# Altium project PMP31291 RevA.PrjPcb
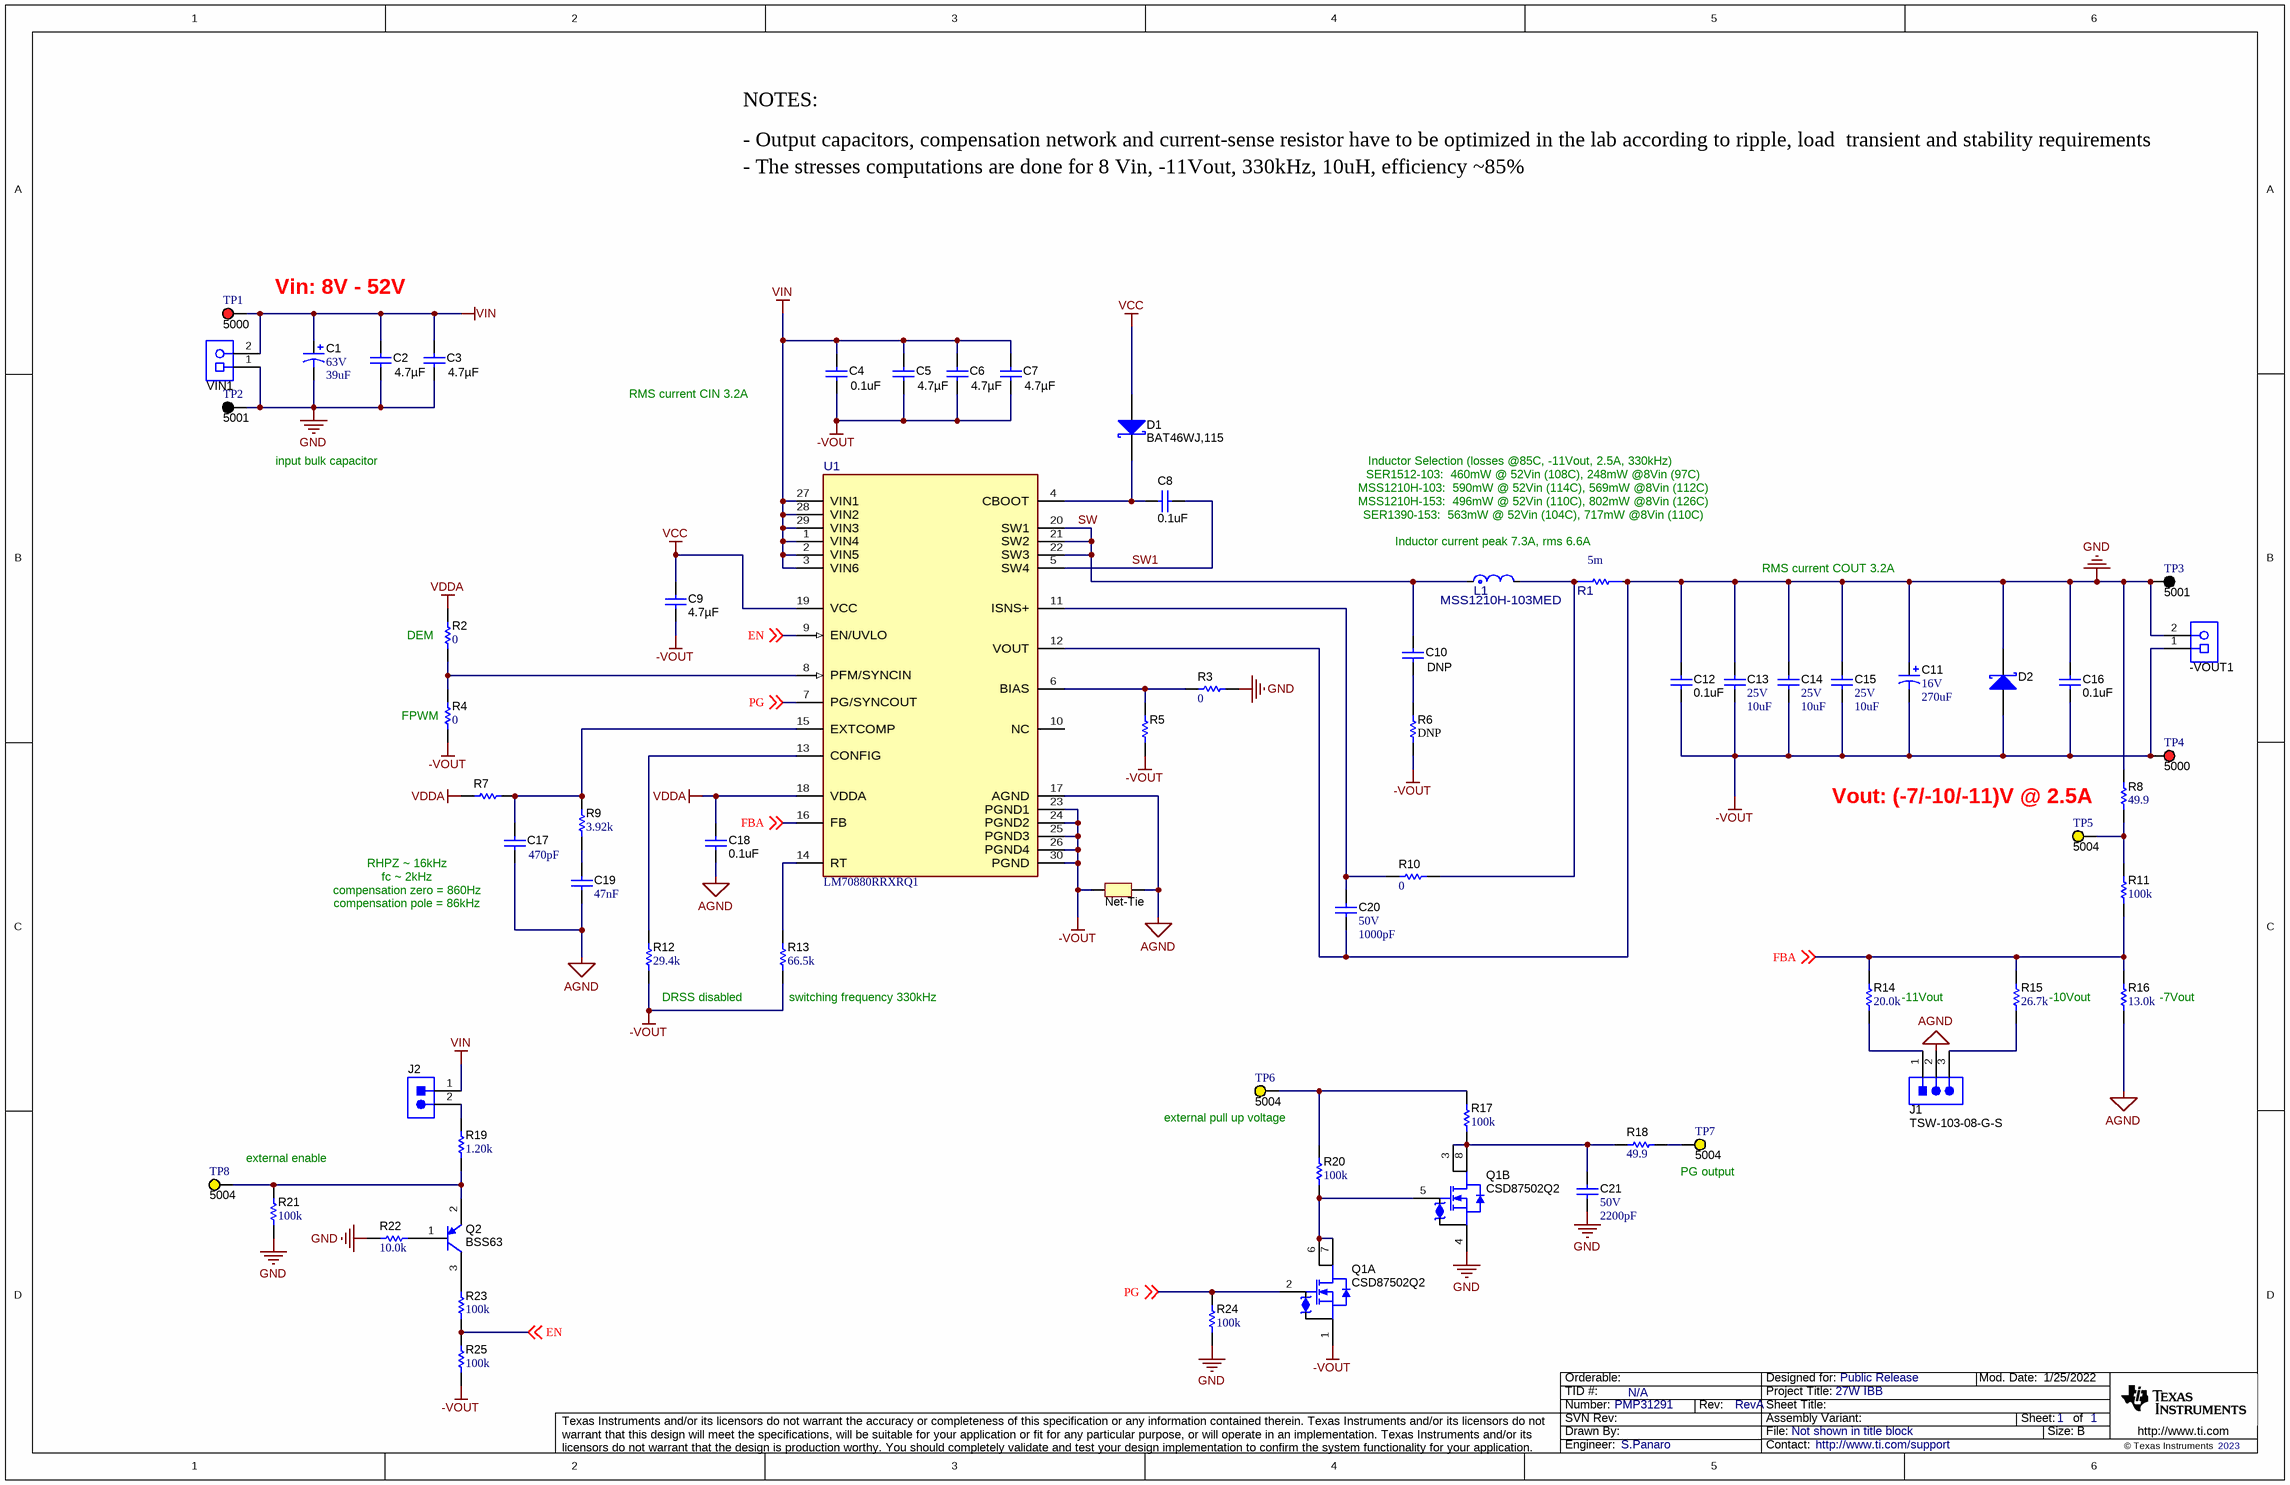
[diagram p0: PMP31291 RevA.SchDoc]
CopyrightYear: 2023; PCB_Layout: S.Panaro; PCB_Rev: RevA; PRJ_Customer: Public Release; PRJ_Engineer: S.Panaro; PRJ_Number: PMP31291; PRJ_Title: 27W IBB; SCH_Rev: RevA; TechSupport: http://www.ti.com/support; TID: N/A
1 sheet, 65 parts. Net scope: global (net labels, ports and power ports of the same name join across sheets).
Board file: PMP31291 RevA.PcbDoc

## Sheet PMP31291 RevA.SchDoc
size 431 x 279 mm; Date: Not shown in title block; ApprovedBy: Not shown in title block; CheckedBy: Not shown in title block; Author: Not shown in title block; CompanyName: Not shown in title block; Engineer: Not shown in title block; Organization: Not shown in title block; Address1: Not shown in title block; Address2: Not shown in title block; Address3: Not shown in title block; Address4: Not shown in title block; DocumentNumber: 1; Revision: Use project parameter SCH_Rev; SheetNumber: 1; SheetTotal: 1; PageSetup: Record=PageOptions¦CenterHorizontal=True¦CenterVertical=True¦PrintScale=1.00¦XCorrection=1.00¦YCorrection=1.00¦PrintKind=0¦BorderSize=5000000¦LeftOffset=0¦BottomOffset=0¦Orientation=2¦PaperLength=1000¦PaperWidth=1000¦Scale=100¦PaperSource=15¦PrintQuality=600¦MediaType=1¦DitherType=10¦PaperKind=Letter¦PrintScaleMode=1

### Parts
-VOUT1  ED120/2DS  [On-Shore_ED120_2DS]  (value not drawn)
C1  VDC_V: 63V  ValueDisplayed: 39uF  [SXV_E12]  (hidden comment: 63SXV39M)
C2  ValueDisplayed: 4.7µF  [1210_220L]  (hidden comment: CL32Y475KCIVPNE)
C3  ValueDisplayed: 4.7µF  [1210_220L]  (hidden comment: CL32Y475KCIVPNE)
C4  value 0.1uF  [0603_HV]  (hidden comment: GCJ188R72A104KA01D)
C5  ValueDisplayed: 4.7µF  [1210_220L]  (hidden comment: CL32Y475KCIVPNE)
C6  ValueDisplayed: 4.7µF  [1210_220L]  (hidden comment: CL32Y475KCIVPNE)
C7  ValueDisplayed: 4.7µF  [1210_220L]  (hidden comment: CL32Y475KCIVPNE)
C8  ValueDisplayed: 0.1uF  [0402L]  (hidden comment: GRM155R71E104KE14D)
C9  Cap_F: 4.7µF  [0603L]  (hidden comment: GRM188Z71A475ME15D)
C10  ValueDisplayed: DNP  [0603_HV]  (hidden comment: GRM1885C2A101JA01D)
C11  VDC_V: 16V  ValueDisplayed: 270uF  [SM_RADIAL_6.3AMM]  (hidden comment: 16SVPG270MX)
C12  ValueDisplayed: 0.1uF  [0402L]  (hidden comment: GRM155R71E104KE14D)
C13  VDC_V: 25V  ValueDisplayed: 10uF  [1206_180]  (hidden comment: CL31B106KAHVPNE)
C14  VDC_V: 25V  ValueDisplayed: 10uF  [1206_180]  (hidden comment: CL31B106KAHVPNE)
C15  VDC_V: 25V  ValueDisplayed: 10uF  [1206_180]  (hidden comment: CL31B106KAHVPNE)
C16  ValueDisplayed: 0.1uF  [0402L]  (hidden comment: GRM155R71E104KE14D)
C17  ValueDisplayed: 470pF  [0402]  (hidden comment: GCM155R71H471KA37D)
C18  ValueDisplayed: 0.1uF  [0402L]  (hidden comment: GRM155R71E104KE14D)
C19  Cap_F: 47nF  [0603]  (hidden comment: GCM188R71E473KA37D)
C20  VDC_V: 50V  ValueDisplayed: 1000pF  [0402]  (hidden comment: CGA2B2C0G1H102J050BA)
C21  VDC_V: 50V  ValueDisplayed: 2200pF  [0402]  (hidden comment: CL05B222JB5NNNC)
D1  BAT46WJ,115  [SOD-323F]
D2  BAT54T1G  [SOD-123]  (value not drawn)
J1  TSW-103-08-G-S  [Samtec_TSW-103-08-x-S]
J2  961102-6804-AR  [3M_961102-68]  (value not drawn)
L1  MSS1210H-103MED  [FP-MSS1210H-103MED_SMT2_12MM0_12MM0-MFG]
NT1  Net-Tie  [Net-Tie_10milWide_30milLong]  (net tie, no BOM)
Q1  CSD87502Q2  [DQK0006B]  (parts A,B of 2)
Q2  BSS63  [SOT-23]
R1  value 5m  [FP-RLM-1632W-4F-R005-FNH_0612-MFG]  (hidden comment: ERJB2DJR005V)
R2  ValueDisplayed: 0  [0402]  (hidden comment: MCR01MZPJ000)
R3  ValueDisplayed: 0  [0402]  (hidden comment: MCR01MZPJ000)
R4  ValueDisplayed: 0  [0402]  (hidden comment: MCR01MZPJ000)
R5  MCR01MZPJ000  [0402]  (value not drawn)
R6  ValueDisplayed: DNP  [0603_HV]  (hidden comment: CRCW06032R00FKEA)
R7  RC1005F104CS  [0402]  (value not drawn)
R8  ValueDisplayed: 49.9  [0402]  (hidden comment: RC0402FR-0749R9L)
R9  ValueDisplayed: 3.92k  [0402]  (hidden comment: CRCW04023K92FKED)
R10  ValueDisplayed: 0  [0402]  (hidden comment: MCR01MZPJ000)
R11  ValueDisplayed: 100k  [0402]  (hidden comment: RC1005F104CS)
R12  ValueDisplayed: 29.4k  [0402]  (hidden comment: CRCW040229K4FKED)
R13  ValueDisplayed: 66.5k  [0402]  (hidden comment: CRCW040266K5FKED)
R14  ValueDisplayed: 20.0k  [0402]  (hidden comment: CRCW040220K0FKED)
R15  ValueDisplayed: 26.7k  [0402]  (hidden comment: CRCW040226K7FKED)
R16  ValueDisplayed: 13.0k  [0402]  (hidden comment: CRCW040213K0FKED)
R17  ValueDisplayed: 100k  [0402]  (hidden comment: RC1005F104CS)
R18  ValueDisplayed: 49.9  [0402]  (hidden comment: RC0402FR-0749R9L)
R19  ValueDisplayed: 1.20k  [0603_HV]  (hidden comment: RC0603FR-071K2L)
R20  ValueDisplayed: 100k  [0402]  (hidden comment: RC1005F104CS)
R21  ValueDisplayed: 100k  [0603_HV]  (hidden comment: RC0603FR-07100KL)
R22  ValueDisplayed: 10.0k  [0603_HV]  (hidden comment: M55342K12B10E0T)
R23  ValueDisplayed: 100k  [0603_HV]  (hidden comment: RC0603FR-07100KL)
R24  ValueDisplayed: 100k  [0402]  (hidden comment: RC1005F104CS)
R25  ValueDisplayed: 100k  [0603_HV]  (hidden comment: RC0603FR-07100KL)
TP1  5000  [Keystone5000]
TP2  5001  [Keystone5001]
TP3  5001  [Keystone5001]
TP4  5000  [Keystone5000]
TP5  5004  [Keystone5004]
TP6  5004  [Keystone5004]
TP7  5004  [Keystone5004]
TP8  5004  [Keystone5004]
U1  LM70880RRXRQ1  [RRX0029B-MFG]
VIN1  ED120/2DS  [On-Shore_ED120_2DS]  (value not drawn)

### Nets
-VOUT: -VOUT1.1 C4.2 C5.2 C6.2 C7.2 C9.2 C11.2(-) C12.1 C13.2 C14.2 C15.2 C16.1 D2.2(A) NT1.1 Q1.1(S1) R4.1 R5.1 R6.2 R12.1 R13.1 R25.1 TP4.1 U1.23(PGND1) U1.24(PGND2) U1.25(PGND3) U1.26(PGND4) U1.30(PGND)
AGND: C17.2 C18.1 C19.2 J1.2 NT1.2 R16.1 U1.17(AGND)
GND: -VOUT1.2 C1.2(-) C2.2 C3.2 C11.1(+) C12.2 C13.1 C14.1 C15.1 C16.2 C20.2 C21.2 D2.1(K) Q1.4(S2) R1.2 R3.2 R8.2 R21.1 R22.1 R24.1 TP2.1 TP3.1 U1.12(VOUT) VIN1.1
VCC: C9.1 D1.2(A) U1.19(VCC)
VDDA: C18.2 R2.2 R7.2 U1.18(VDDA)
VIN: C1.1(+) C2.1 C3.1 C4.1 C5.1 C6.1 C7.1 J2.1 TP1.1 U1.1(VIN4) U1.2(VIN5) U1.3(VIN6) U1.27(VIN1) U1.28(VIN2) U1.29(VIN3) VIN1.2
CONFIG: R12.2 U1.13(CONFIG)
EN: R23.1 R25.2 U1.9(EN/UVLO) ; off-sheet EN
FBA: R11.1 R14.2 R15.2 R16.2 U1.16(FB) ; off-sheet FBA
PG: Q1.2(G1) R24.2 U1.7(PG/SYNCOUT) ; off-sheet PG
RT: R13.2 U1.14(RT)
SW: C10.1 L1.1 U1.20(SW1) U1.21(SW2) U1.22(SW3)
SW1: C8.2 U1.5(SW4)
NetC8_1: C8.1 D1.1(K) U1.4(CBOOT)
NetC10_2: C10.2 R6.1
NetC17_1: C17.1 R7.1 R9.2 U1.15(EXTCOMP)
NetC19_1: C19.1 R9.1
NetC20_1: C20.1 R10.1 U1.11(ISNS+)
NetC21_1: C21.1 Q1.3(D2) Q1.8(D2) R17.1 R18.2
NetJ1_1: J1.1 R14.1
NetJ1_3: J1.3 R15.1
NetJ2_2: J2.2 R19.2
NetL1_2: L1.2 R1.1 R10.2
NetQ1_5: Q1.5(G2) Q1.6(D1) Q1.7(D1) R20.1
NetQ2_1: Q2.1(B) R22.2
NetQ2_2: Q2.2(E) R19.1 R21.2 TP8.1
NetQ2_3: Q2.3(C) R23.2
NetR2_1: R2.1 R4.2 U1.8(PFM/SYNCIN)
NetR3_1: R3.1 R5.2 U1.6(BIAS)
NetR8_1: R8.1 R11.2 TP5.1
NetR17_2: R17.2 R20.2 TP6.1
NetR18_1: R18.1 TP7.1

Not connected (* = marked no-connect by the designer): U1 10(NC)

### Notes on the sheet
- NOTES:
- - Output capacitors, compensation network and current-sense resistor have to be optimized in the lab according to ripple, load  transient and stability requirements
- - The stresses computations are done for 8 Vin, -11Vout, 330kHz, 10uH, efficiency ~85%
- Vin: 8V - 52V
- RMS current CIN 3.2A
- input bulk capacitor
- Inductor Selection (losses @85C, -11Vout, 2.5A, 330kHz)
- SER1512-103:  460mW @ 52Vin (108C), 248mW @8Vin (97C)
- MSS1210H-103:  590mW @ 52Vin (114C), 569mW @8Vin (112C)
- MSS1210H-153:  496mW @ 52Vin (110C), 802mW @8Vin (126C)
- Inductor current peak 7.3A, rms 6.6A
- SER1390-153:  563mW @ 52Vin (104C), 717mW @8Vin (110C)
- RMS current COUT 3.2A
- (near R2) DEM
- (near R4) FPWM
- Vout: (-7/-10/-11)V @ 2.5A
- RHPZ ~ 16kHz
- fc ~ 2kHz
- (near C17) compensation zero = 860Hz
- compensation pole = 86kHz
- (near R12) DRSS disabled
- (near R13) switching frequency 330kHz
- (near R14) -11Vout
- -10Vout
- (near R16) -7Vout
- external enable
- (near TP6) external pull up voltage
- PG output
- Labels drawn without touching a wire or pin: EN/UVLO

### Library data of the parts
-VOUT1 VIN1 = CMP-0074910-1: Terminal Block, 5.08 mm, 2x1, Brass, TH; Manufacturer: On-Shore Technology; Cert_VDE: Y; CNHeader: False; Current_A: 15A; Green_Lifecycle: Not Set; Shrouded: N; Gender: Female; Green_REACh: Incomplete; Voltage_V: 300V; Row_Count: 1; Pitch_mm: 5.08; CT: True
C1 = CMP-0012145-3: CAP, Aluminum Polymer, 39 uF, 63 V, +/- 20%, 0.025 ohm, 8.0x11.9mm SMD; Manufacturer: Panasonic; TaMin_C: -55°C; ESR_ohm: 25m; Polarized: Y; Value: 39uF; TaMax_C: 105°C; CompType: Capacitor; Cap_F: 39µF; IRMS_A: 2.95A; AEC Category: Q200
C2 C3 C5-C7 = CMP-0082268-1: CAP, CERM, 4.7 µF, 100 V,+/- 10%, X7S, AEC-Q200 Grade 1, 1210; Value: 4.7uF; Value2: 100V
C4 = CMP-0064935-4: CAP, CERM, 0.1 uF, 100 V,+/- 10%, X7R, AEC-Q200 Grade 1, 0603; Manufacturer: MuRata; TaMin_C: -55°C; Polarized: N; SizeAreaWB_mm2: 4.68; Value1: Unknown; U/M: EA; TaMax_C: 125°C; SizeZ_mm: 1; SizeX_mm: 1.6; SizeY_mm: 0.8; Cap_Case: 0603; Value2: 100V; SizeArea_mm2: 1.28; AEC Qualified: Y; Cap_F: 100nF; AEC Category: Q200
C8 C12 C16 C18 = CMP-0006659-2: CAP, CERM, 0.1 uF, 25 V, +/- 10%, X7R, 0402; Manufacturer: MuRata; Polarized: N; Value: 0.1uF; U/M: EA; Cap_F: 100nF; Value1: Unknown; VDC_V: 25V; TaMin_C: -55°C; TaMax_C: 125°C; Cap_Case: 0402; AEC Category: Q200; SizeArea_mm2: 0.5; SizeAreaWB_mm2: 3; SizeX_mm: 1; SizeZ_mm: 0.6
C9 = CMP-0007498-4: CAP, CERM, 4.7 uF, 10 V, +/- 20%, X7R, 0603; Manufacturer: MuRata; Polarized: N; Value: 4.7uF; U/M: EA; Value1: Unknown; VDC_V: 10V; TaMin_C: -55°C; TaMax_C: 125°C; Cap_Case: 0603; AEC Category: Q200; SizeArea_mm2: 1.28; SizeAreaWB_mm2: 4.68; SizeX_mm: 1.6; SizeY_mm: 0.8; SizeZ_mm: 1
C10 = CMP-0007237-4: CAP, CERM, 100 pF, 100 V, +/- 5%, C0G/NP0, 0603; Manufacturer: MuRata; TaMin_C: -55°C; Polarized: N; SizeAreaWB_mm2: 4.68; Value1: Unknown; U/M: EA; Value: 100pF; TaMax_C: 125°C; SizeZ_mm: 1; SizeX_mm: 1.6; SizeY_mm: 0.8; Cap_Case: 0603; Value2: 100V; SizeArea_mm2: 1.28; AEC Category: Q200
C11 = CMP-0012070-3: CAP, Aluminum Polymer, 270 uF, 16 V, +/- 20%, 10 mohm, 6.3x7.9 SMD; Manufacturer: Panasonic; Value: 270uF; Cap_F: 270µF; IRMS_A: 5.08A
C13-C15 = CMP-0008965-2: CAP, CERM, 10 uF, 25 V, +/- 10%, X7R, 1206; TaMin_C: -55°C; Value: 10uF; Cap_F: 10µF; AEC Category: Q200
C17 = CMP-0006360-2: CAP, CERM, 470 pF, 50 V, +/- 10%, X7R, AEC-Q200 Grade 1, 0402; Manufacturer: MuRata; TaMin_C: -55°C; Polarized: N; SizeAreaWB_mm2: 3; Value1: Unknown; U/M: EA; Value: 470pF; TaMax_C: 125°C; SizeZ_mm: 0.6; SizeX_mm: 1; SizeY_mm: 0.5; Value2: 50V; AEC Qualified: Y; AEC Category: Q200
C19 = CMP-0007141-5: CAP, CERM, 0.047 uF, 25 V, +/- 10%, X7R, AEC-Q200 Grade 1, 0603; Manufacturer: MuRata; TaMin_C: -55°C; Polarized: N; SizeAreaWB_mm2: 4.68; Value1: Unknown; U/M: EA; TaMax_C: 125°C; SizeZ_mm: 1; SizeX_mm: 1.6; SizeY_mm: 0.8; Value2: 25V; SizeArea_mm2: 1.28; AEC Qualified: Y; AEC Category: Q200
C20 = CMP-0006309-2: CAP, CERM, 1000 pF, 50 V, +/- 5%, C0G/NP0, AEC-Q200 Grade 1, 0402; Manufacturer: TDK; TaMin_C: -55°C; Polarized: N; SizeAreaWB_mm2: 3; Value1: Unknown; U/M: EA; Value: 1000pF; TaMax_C: 125°C; SizeZ_mm: 0.6; SizeX_mm: 1; SizeY_mm: 0.5; AEC Qualified: Y; Cap_F: 1nF; AEC Category: Q200
C21 = CMP-0006344-2: CAP, CERM, 2200 pF, 50 V, +/- 5%, X7R, 0402; Manufacturer: Samsung Electro-Mechanics; TaMin_C: -55°C; Polarized: N; SizeAreaWB_mm2: 3; Value1: Unknown; U/M: EA; Value: 2200pF; TaMax_C: 125°C; SizeZ_mm: 0.6; SizeX_mm: 1; SizeY_mm: 0.5; Cap_F: 2.2nF; AEC Category: Q200
D1 = CMP-0076946-2: Diode, Schottky, 100 V, 0.25 A, SOD-323F; Manufacturer: Nexperia; SizeAreaWB_mm2: 7.875; Value2: 0.85V; SizeX_mm: 2.5; Green_REACh: Incomplete; SizeArea_mm2: 3.125; Vf_V: 850mV; Green_Lifecycle: Not Set; Vr_V: 100V; TJmax_C: 150°C; Value1: 0.25A; Io_A: 250mA; SizeZ_mm: 0.8; Value: 100V; AEC Category: Q101; SizeY_mm: 1.25
D2 = CMP-0028457-2: Diode, Schottky, 30 V, 0.2 A, SOD-123; Manufacturer: ON Semiconductor; SizeArea_mm2: 6.545; Io_A: 200mA; SizeX_mm: 3.85; Value1: 0.2A; SizeY_mm: 1.7; AEC Category: Q101; Vf_V: 800mV; TJmax_C: 125°C; Green_Lifecycle: Not Set; RJC_CperW: 174; Value: 30V; Value2: 0.8V; SizeAreaWB_mm2: 13.095; Green_REACh: Incomplete; SizeZ_mm: 1.35
J1 = CMP-0079327-1: Header, 2.54mm, 3x1, Gold, TH; Manufacturer: Samtec; Pitch_mm: 2.54; Gender: Male; Cert_UL: Y; Shrouded: N; Row_Count: 1
J2 = CMP-0075355-2: Header, 2.54mm, 2x1, Gold, TH; Manufacturer: 3M; Row_Count: 1; Current_A: 2A; CNHeader: True; Cert_UL: Y; Gender: Male; Pitch_mm: 2.54; MFG_Status: TI_Obsolete; Shrouded: N; CT: False
L1 = CMP-0094344-1: Shielded Power Inductor 10uH ±20% 0.013 Ohms 9.1A; Manufacturer: Coilcraft; Test Frequency: 100kHz; TaMax_C: +125°C; AEC Grade: Grade 1; Material: Ferrite; Ind_H: 10µH; TaMin_C: -40°C; Shrouded: true; Isat: 7.5A; SizeZ_mm: 10.2mm; Self Resonant Frequency: 18MHz; DCR_ohm: 13m; AEC Qualified: Yes
NT1 = CMP-0078142-6: Single point connection between nets.
Q1 = CMP-0000608-1: MOSFET, 2-CH, N-CH, 30 V, 5 A, DQK0006B (WSON-6); Alternate Manufacturer: None; Manufacturer: Texas Instruments; SizeZ_mm: 0.8; ChType: N; Value2: 2.2 nC; Value1: 0.04; VdsMax_V: 30V; SizeX_mm: 2; SizeAreaWB_mm2: 9; Vgs_V: 20V; QgTyp_nC: 2.2; Value: 30V; Rdson45_ohm: 42m; SizeArea_mm2: 4; AEC Category: Q101; IdsMax_A: 5A; U/M: EA
Q2 = CMP-0000366-2: Transistor, PNP, 100 V, 0.2 A, SOT-23; Manufacturer: Fairchild Semiconductor; TaMax_C: 150°C; Value1: 0.2 A; Vcesat1_V: 250mV; SizeX_mm: 2.5; SizeY_mm: 3; TaMin_C: -55°C; IcRated_A: 200mA; CompType: BJT; SizeZ_mm: 1.1; AEC Qualified: N; Value: 100 V; SizeArea_mm2: 7.5; NPN: 0; Vceo_V: 100V; PNP: 1; AEC Category: Q101; SizeAreaWB_mm2: 14; U/M: EA
R1 = CMP-0091128-1: Res 0.005 Ohm
R2-R4 R10 = CMP-0027002-2: RES, 0, 5%, 0.063 W, 0402; Manufacturer: Rohm; Power_W: 63mW; TempCo: 500 ppm/C; Value_Code: 0000; U/M: EA; Value: 0; EIA_Code: E24; SizeX_mm: 1; SizeY_mm: 0.5; SizeZ_mm: 0.6; Value2: 0.063W; VDC_V: 50V; AEC Category: Q200
R5 = CMP-0027002-2: RES, 0, 5%, 0.063 W, 0402; Manufacturer: Rohm; Power_W: 63mW; TempCo: 500 ppm/C; Value_Code: 0000; U/M: EA; Value: 0; EIA_Code: E24; SizeX_mm: 1; SizeY_mm: 0.5; SizeZ_mm: 0.6; Value2: 0.063W; VDC_V: 50V; AEC Category: Q200; ValueDisplayed: DNP
R6 = CMP-0022302-4: RES, 2.00, 1%, 0.1 W, AEC-Q200 Grade 0, 0603; Manufacturer: Vishay-Dale; Power_W: 100mW; TempCo: 100 ppm/C; Value_Code: 2R00; Value: 2.00; EIA_Code: E96; Res_ohm: 2; SizeX_mm: 1.6; SizeY_mm: 0.8; SizeZ_mm: 1; Value2: 0.1W; SizeArea_mm2: 1.28; AEC Qualified: Y; VDC_V: 75V; AEC Category: Q200; AEC Grade: 0
R7 = CMP-0026745-1: RES, 100 k, 1%, 0.063 W, 0402; Manufacturer: Samsung Electro-Mechanics; Power_W: 63mW; TempCo: 100 ppm/C; Value_Code: 100k; U/M: EA; Value: 100k; EIA_Code: E96; SizeX_mm: 1; SizeY_mm: 0.5; SizeZ_mm: 0.6; Value2: 0.063W; AEC Qualified: N; VDC_V: 80V; AEC Category: Q200; ValueDisplayed: DNP
R8 R18 = CMP-0026738-1: RES, 49.9, 1%, 0.063 W, 0402; Manufacturer: Yageo America; Power_W: 63mW; TempCo: 100 ppm/C; Value_Code: 49R9; U/M: EA; Value: 49.9; EIA_Code: E96; SizeX_mm: 1; SizeY_mm: 0.5; SizeZ_mm: 0.6; Value2: 0.063W; AEC Qualified: N; VDC_V: 50V; AEC Category: Q200
R9 = CMP-0026340-2: RES, 3.92 k, 1%, 0.063 W, AEC-Q200 Grade 0, 0402; Manufacturer: Vishay-Dale; Power_W: 63mW; TempCo: 100 ppm/C; Value_Code: 3k92; Value: 3.92k; EIA_Code: E96; SizeX_mm: 1; SizeY_mm: 0.5; SizeZ_mm: 0.6; Value2: 0.063W; AEC Qualified: Y; VDC_V: 50V; AEC Category: Q200; AEC Grade: 0
R11 R17 R20 R24 = CMP-0026745-1: RES, 100 k, 1%, 0.063 W, 0402; Manufacturer: Samsung Electro-Mechanics; Power_W: 63mW; TempCo: 100 ppm/C; U/M: EA; Value: 100k; EIA_Code: E96; SizeX_mm: 1; SizeY_mm: 0.5; SizeZ_mm: 0.6; Value2: 0.063W; AEC Qualified: N; VDC_V: 80V; AEC Category: Q200
R12 = CMP-0026225-2: RES, 29.4 k, 1%, 0.063 W, AEC-Q200 Grade 0, 0402; Manufacturer: Vishay-Dale; Power_W: 63mW; TempCo: 100 ppm/C; Value_Code: 29k4; Value: 29.4k; EIA_Code: E96; SizeX_mm: 1; SizeY_mm: 0.5; SizeZ_mm: 0.6; Value2: 0.063W; AEC Qualified: Y; VDC_V: 50V; AEC Category: Q200; AEC Grade: 0
R13 = CMP-0026502-2: RES, 66.5 k, 1%, 0.063 W, AEC-Q200 Grade 0, 0402; Manufacturer: Vishay-Dale; Power_W: 63mW; TempCo: 100 ppm/C; Value_Code: 66k5; Value: 66.5k; EIA_Code: E96; SizeX_mm: 1; SizeY_mm: 0.5; SizeZ_mm: 0.6; Value2: 0.063W; AEC Qualified: Y; VDC_V: 50V; AEC Category: Q200; AEC Grade: 0
R14 = CMP-0026162-2: RES, 20.0 k, 1%, 0.063 W, AEC-Q200 Grade 0, 0402; Manufacturer: Vishay-Dale; Power_W: 63mW; TempCo: 100 ppm/C; Value_Code: 20k0; Value: 20.0k; EIA_Code: E96; Res_ohm: 20k; SizeX_mm: 1; SizeY_mm: 0.5; SizeZ_mm: 0.6; Value2: 0.063W; AEC Qualified: Y; VDC_V: 50V; AEC Category: Q200; AEC Grade: 0
R15 = CMP-0026208-2: RES, 26.7 k, 1%, 0.063 W, AEC-Q200 Grade 0, 0402; Manufacturer: Vishay-Dale; Power_W: 63mW; TempCo: 100 ppm/C; Value_Code: 26k7; Value: 26.7k; EIA_Code: E96; SizeX_mm: 1; SizeY_mm: 0.5; SizeZ_mm: 0.6; Value2: 0.063W; AEC Qualified: Y; VDC_V: 50V; AEC Category: Q200; AEC Grade: 0
R16 = CMP-0026003-3: RES, 13.0 k, 1%, 0.063 W, AEC-Q200 Grade 0, 0402; Manufacturer: Vishay-Dale; Power_W: 63mW; TempCo: 100 ppm/C; Value_Code: 13k0; Value: 13.0k; EIA_Code: E96; Res_ohm: 13k; SizeX_mm: 1; SizeY_mm: 0.5; SizeZ_mm: 0.6; Value2: 0.063W; AEC Qualified: Y; VDC_V: 50V; AEC Category: Q200; AEC Grade: 0
R19 = CMP-0022874-5: RES, 1.20 k, 1%, 0.1 W, 0603; Manufacturer: Yageo; Power_W: 100mW; TempCo: 100 ppm/C; Value_Code: 1k20; Value: 1.20k; Res_ohm: 1.2k; SizeX_mm: 1.6; SizeY_mm: 0.8; SizeZ_mm: 1; Value2: 0.1W; SizeArea_mm2: 1.28; AEC Qualified: N; VDC_V: 75V; AEC Category: Q200; SizeAreaWB_mm2: 4.68
R21 R23 R25 = CMP-0022735-5: RES, 100 k, 1%, 0.1 W, 0603; Manufacturer: Yageo; Power_W: 100mW; TempCo: 100 ppm/C; Value: 100k; EIA_Code: E96; SizeX_mm: 1.6; SizeY_mm: 0.8; SizeZ_mm: 1; Value2: 0.1W; SizeArea_mm2: 1.28; AEC Qualified: N; VDC_V: 75V; AEC Category: Q200; SizeAreaWB_mm2: 4.68
R22 = CMP-0080488-1: RES, 10.0 k, 1%, 0.1 W, 0603; Manufacturer: TT Electronics/IRC; Power_W: 100mW; TempCo: 100 ppm/C; SizeAreaWB_mm2: 4.68; Value_Code: 10k0; Value: 10.0k; EIA_Code: E96; Res_ohm: 10k; SizeX_mm: 1.6; SizeY_mm: 0.8; SizeZ_mm: 1; Value2: 0.1W; SizeArea_mm2: 1.28; AEC Qualified: N; AEC Category: Q200
TP1 TP4 = CMP-0055137-2: Test Point, Miniature, Red, TH; Manufacturer: Keystone Electronics; Green_REACh: Passed; Green_Lifecycle: Active; ContactFinish: Silver; CNHeader: FALSE; CT: TRUE
TP2 TP3 = CMP-0055138-2: Test Point, Miniature, Black, TH; Manufacturer: Keystone Electronics; ContactFinish: Silver; CNHeader: FALSE; Green_Lifecycle: Active; Green_REACh: Passed; CT: TRUE
TP5-TP8 = CMP-0055141-2: Test Point, Miniature, Yellow, TH; Manufacturer: Keystone Electronics; CT: TRUE; ContactFinish: Silver; Green_Lifecycle: Active; CNHeader: FALSE; Green_REACh: Passed
U1 = CMP-0096026-3: 80-V, 8-A Synchronous DC/DC Buck Converter With Ultra-Low IQ, VQFN29; Manufacturer: Texas Instruments; Number Of Outputs: 1; Switching Frequency: 0.2-2.2MHz; SizeZ_mm: 1mm; Output Voltage: 0.8-55V; Output Type: AdjustableProgrammable; AEC Qualified: Yes; AEC Grade: Grade 1; TaMin_C: -40°C; TaMax_C: +125°C; Standoff Height: 0mm; Min Supply Voltage: 4.5V; Max Supply Voltage: 80V; TJmax_C: +150°C; CompType: IC; AEC Category: Q200

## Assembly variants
001: not fitted C7 C10 C15 R2 R5 R6 R7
